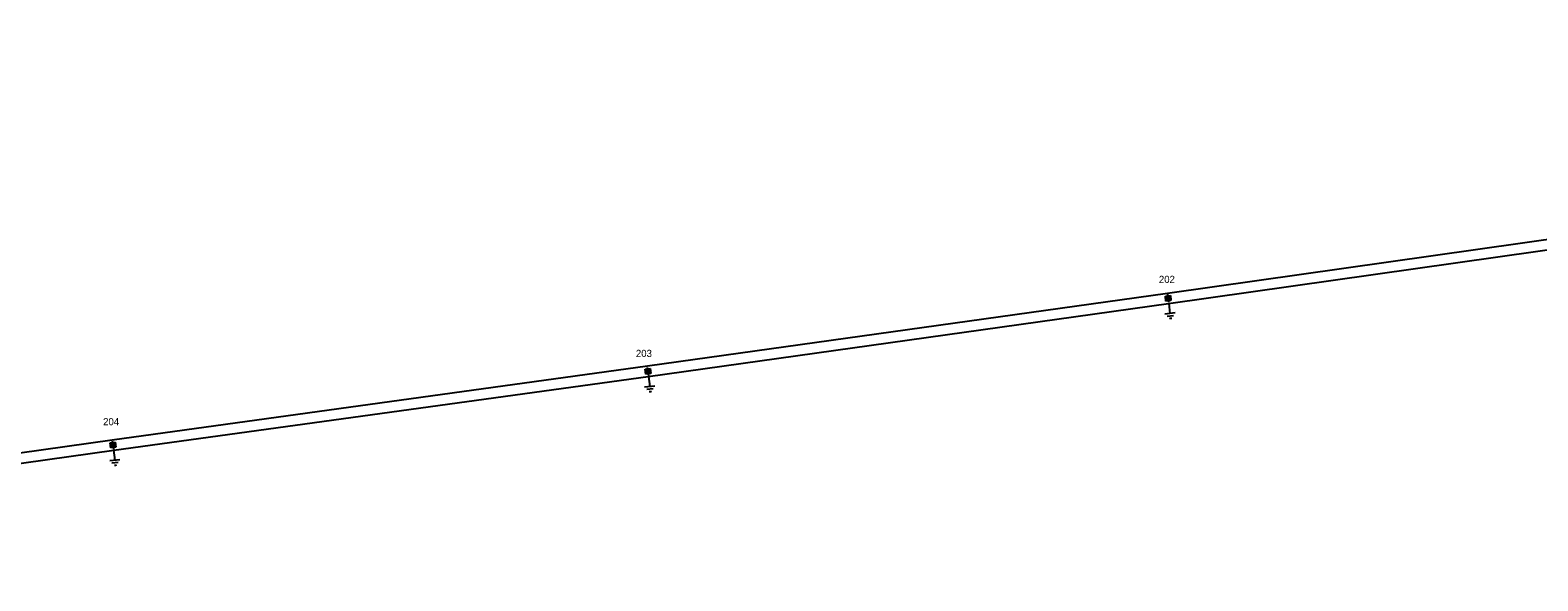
# Model space of a CAD drawing. Extents: x -545588 to -543214, y -1196037 to -1194452.
# Drawn here: x -544817.1 to -544449.4, y -1194901.6 to -1194767.3 of the extents above; entities that cross this region are included whole.
import ezdxf

# ---------------------------------------------------------------- set-up
doc = ezdxf.new("R2010")
doc.units = 0
for name, color, linetype in [('Vrstva 1', 7, 'Continuous'), ('Vrstva 13', 7, 'Continuous'), ('Vrstva 14', 7, 'Continuous'), ('Vrstva 15', 7, 'Continuous'), ('Vrstva 2', 7, 'Continuous')]:
    doc.layers.add(name, color=color, linetype=linetype)

# ---------------------------------------------------------------- blocks, each defined once
blk = doc.blocks.new('VN810')
at = {"layer": 'Vrstva 14'}
for points in [[(0, -1.25), (0, -3.75)], [(1.25, -3.75), (-1.25, -3.75)], [(0.77, -4.37), (-0.8, -4.37)], [(0, -5), (-0.25, -5)], [(0.27, -5), (0, -5)]]:
    blk.add_lwpolyline(points, dxfattribs=at)
blk = doc.blocks.new('VN470')
at = {"layer": 'Vrstva 2'}
for points in [[(-1.23, 1.22), (1.23, 1.22)], [(-1.23, -1.23), (-1.23, 1.22)], [(-0.92, 0.9), (0.92, 0.9)], [(-0.92, -0.95), (-0.92, 0.9)], [(-0.61, 0.61), (0.61, 0.61)], [(-0.61, -0.62), (-0.61, 0.61)], [(-0.31, -0.27), (-0.31, 0.34)], [(-0.31, 0.34), (0.31, 0.34)], [(0, 1.22), (0, 1.97)], [(0.31, 0.34), (0.31, -0.27)], [(0.61, 0.61), (0.61, -0.62)], [(0.92, 0.9), (0.92, -0.95)], [(1.23, 1.22), (1.23, -1.23)], [(1.23, -1.23), (-1.23, -1.23)], [(0.92, -0.95), (-0.92, -0.95)], [(0.61, -0.62), (-0.61, -0.62)], [(0.31, -0.27), (-0.31, -0.27)], [(0, -1.23), (0, -1.98)]]:
    blk.add_lwpolyline(points, dxfattribs=at)

msp = doc.modelspace()

# ---------------------------------------------------------------- linework, layer by layer
at = {"layer": 'Vrstva 1'}
for points in [[(-544083.88, -1194767.33), (-544137.68, -1194774.97), (-544275.32, -1194794.17), (-544399.3, -1194811.66), (-544539.71, -1194831.51), (-544666.5, -1194849.29), (-544797.03, -1194867.27), (-544922.4, -1194884.94), (-545023.84, -1194899.15), (-545076.32, -1194876.08), (-545112.71, -1194859.53)], [(-545068.12, -1194888.96), (-545023.6, -1194901.6), (-544922.06, -1194887.4), (-544796.64, -1194869.77), (-544666.32, -1194851.78), (-544539.47, -1194833.99), (-544398.96, -1194814.1), (-544275.11, -1194796.62), (-544137.43, -1194777.48), (-544081.81, -1194769.58)]]:
    msp.add_lwpolyline(points, dxfattribs=at)

# ---------------------------------------------------------------- block references
at = {"layer": 'Vrstva 13'}
for p, xscale, yscale, rotation in [((-544539.57, -1194832.7), 0.5000000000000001, 0.5, 6.796644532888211), ((-544666.42, -1194850.52), 0.49999999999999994, 0.4999999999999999, 6.796644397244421), ((-544796.84, -1194868.49), 0.49999999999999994, 0.4999999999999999, 6.796644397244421)]:
    msp.add_blockref('VN470', p, dxfattribs=dict(at, xscale=xscale, yscale=yscale, rotation=rotation))
at = {"layer": 'Vrstva 15'}
for p, rotation in [((-544539.57, -1194832.7), 6.796644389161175), ((-544666.42, -1194850.52), 6.796644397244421), ((-544796.84, -1194868.49), 6.791966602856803)]:
    msp.add_blockref('VN810', p, dxfattribs=dict(at, rotation=rotation))

# ---------------------------------------------------------------- texts
at = {"layer": 'Vrstva 14'}
for s, p in [('202', (-544541.83, -1194828.97)), ('203', (-544669.35, -1194847.02)), ('204', (-544799.26, -1194863.66))]:
    msp.add_text(s, height=1.75, dxfattribs=at).set_placement(p)

doc.saveas('drawing.dxf')
